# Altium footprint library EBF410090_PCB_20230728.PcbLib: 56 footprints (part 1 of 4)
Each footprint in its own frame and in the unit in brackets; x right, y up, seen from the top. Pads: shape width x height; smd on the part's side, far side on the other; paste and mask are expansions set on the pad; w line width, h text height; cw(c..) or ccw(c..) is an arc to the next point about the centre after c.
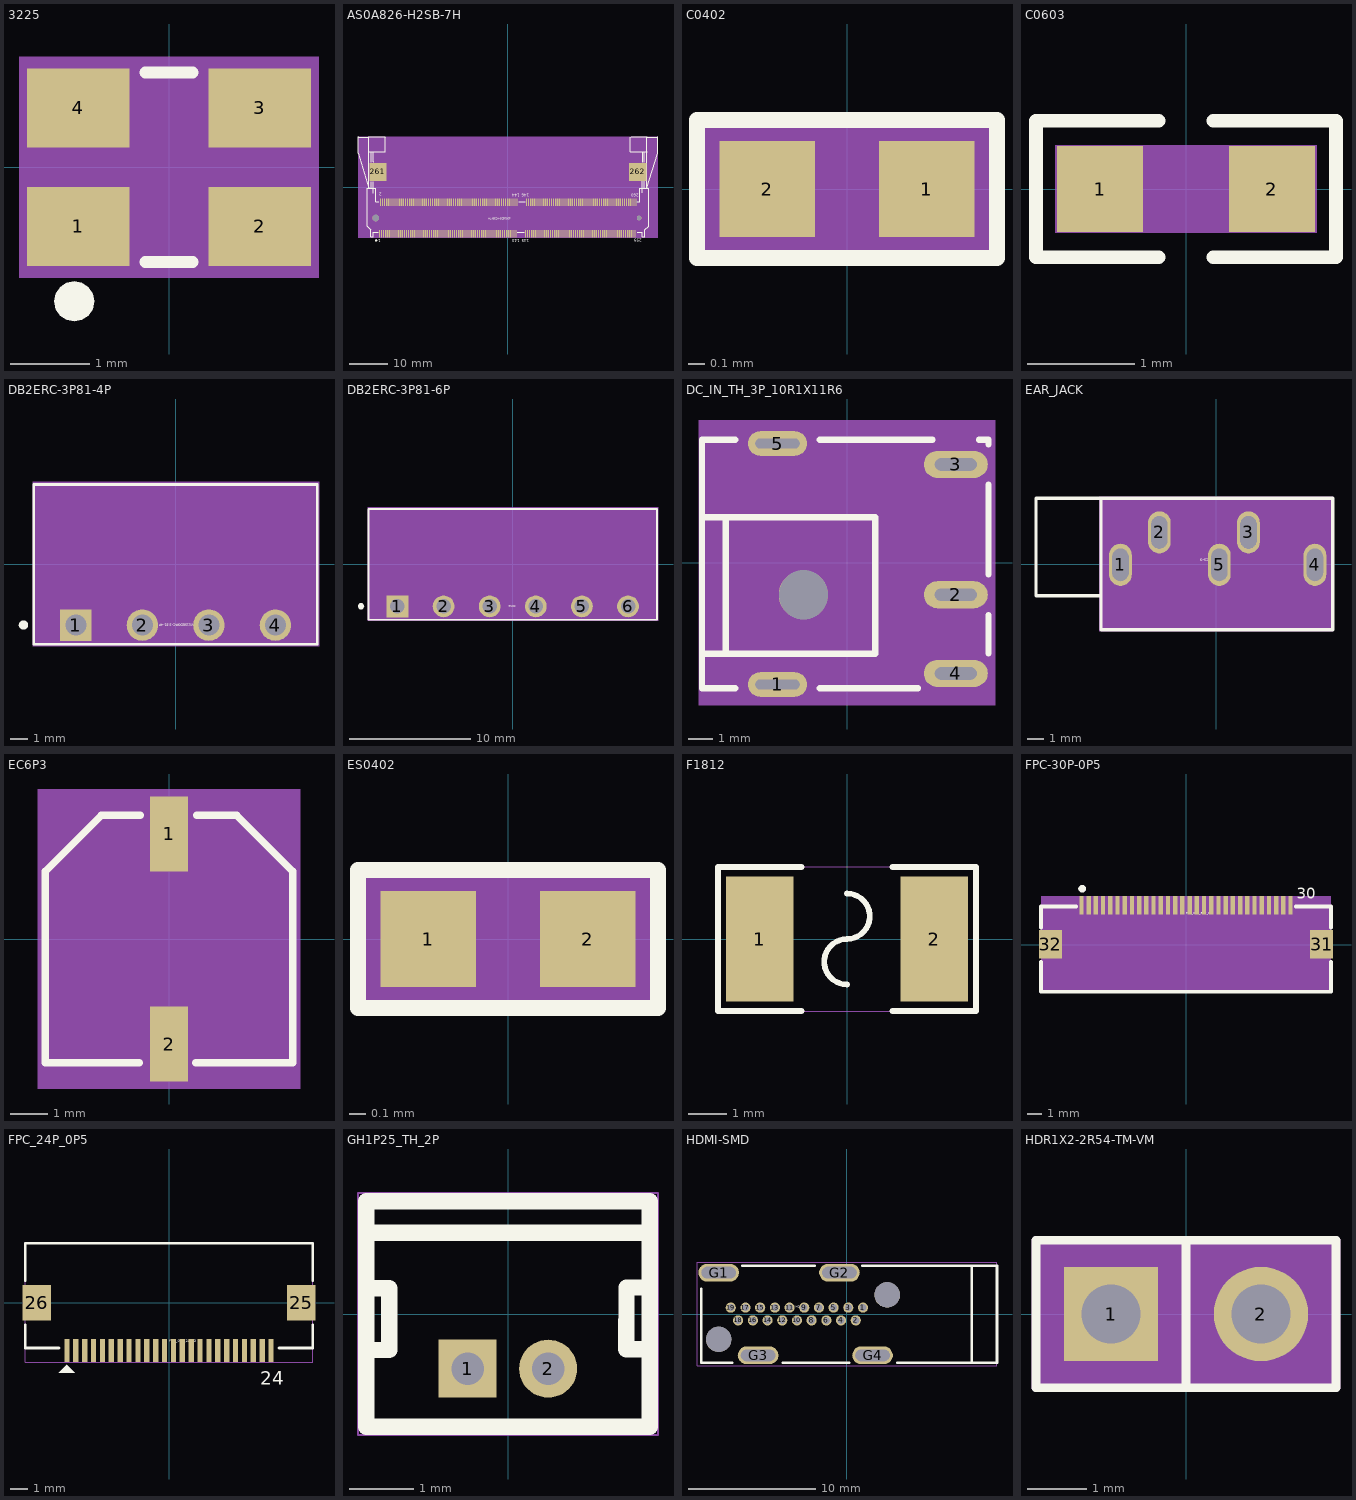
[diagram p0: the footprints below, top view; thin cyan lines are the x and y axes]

## 3225 [mm] "3225"
pads (4):
  rect 1.3x1 smd: 1(-1.15,-0.75) 2(1.15,-0.75) 3(1.15,0.75) 4(-1.15,0.75)
Top Overlay:
  dashed: -0.945,-1.7 -0.964,-1.603 -1.02,-1.52 -1.102,-1.465 -1.2,-1.445 -1.297,-1.465 -1.325,-1.483 -1.38,-1.52 -1.435,-1.603 -1.455,-1.7 -1.435,-1.798 -1.38,-1.88 -1.325,-1.917 -1.297,-1.935 -1.2,-1.955 -1.102,-1.935 -1.02,-1.88 -0.964,-1.798
  lines w0.15: -0.3,-1.2 0.3,-1.2 ; -0.3,1.2 0.3,1.2
Top 3D Body:
  region: -1.9,1.4 -1.9,-1.4 1.9,-1.4 1.9,1.4
Top Assembly:
  lines w0.15: -1.6,-1.25 1.6,-1.25 1.6,1.25 -1.6,1.25 -1.6,-1.25
3D body: height 3.81, standoff 0, extent -1.9,-1.4 1.9,1.4

## AS0A826-H2SB-7H [mm] "AS0A826-H2SB-7H"
pads (264):
  rect 0.3x2 smd: 1(-33.425,-12.1) 2(-33.175,-3.9) 3(-32.925,-12.1) 4(-32.675,-3.9) 5(-32.425,-12.1) 6(-32.175,-3.9) 7(-31.925,-12.1) 8(-31.675,-3.9) 9(-31.425,-12.1) 10(-31.175,-3.9) 11(-30.925,-12.1) 12(-30.675,-3.9) 13(-30.425,-12.1) 14(-30.175,-3.9) 15(-29.925,-12.1) 16(-29.675,-3.9) 17(-29.425,-12.1) 18(-29.175,-3.9) 19(-28.925,-12.1) 20(-28.675,-3.9) 21(-28.425,-12.1) 22(-28.175,-3.9) 23(-27.925,-12.1) 24(-27.675,-3.9) 25(-27.425,-12.1) 26(-27.175,-3.9) 27(-26.925,-12.1) 28(-26.675,-3.9) 29(-26.425,-12.1) 30(-26.175,-3.9) 31(-25.925,-12.1) 32(-25.675,-3.9) 33(-25.425,-12.1) 34(-25.175,-3.9) 35(-24.925,-12.1) 36(-24.675,-3.9) 37(-24.425,-12.1) 38(-24.175,-3.9) 39(-23.925,-12.1) 40(-23.675,-3.9) 41(-23.425,-12.1) 42(-23.175,-3.9) 43(-22.925,-12.1) 44(-22.675,-3.9) 45(-22.425,-12.1) 46(-22.175,-3.9) 47(-21.925,-12.1) 48(-21.675,-3.9) 49(-21.425,-12.1) 50(-21.175,-3.9) 51(-20.925,-12.1) 52(-20.675,-3.9) 53(-20.425,-12.1) 54(-20.175,-3.9) 55(-19.925,-12.1) 56(-19.675,-3.9) 57(-19.425,-12.1) 58(-19.175,-3.9) 59(-18.925,-12.1) 60(-18.675,-3.9) 61(-18.425,-12.1) 62(-18.175,-3.9) 63(-17.925,-12.1) 64(-17.675,-3.9) 65(-17.425,-12.1) 66(-17.175,-3.9) 67(-16.925,-12.1) 68(-16.675,-3.9) 69(-16.425,-12.1) 70(-16.175,-3.9) 71(-15.925,-12.1) 72(-15.675,-3.9) 73(-15.425,-12.1) 74(-15.175,-3.9) 75(-14.925,-12.1) 76(-14.675,-3.9) 77(-14.425,-12.1) 78(-14.175,-3.9) 79(-13.925,-12.1) 80(-13.675,-3.9) 81(-13.425,-12.1) 82(-13.175,-3.9) 83(-12.925,-12.1) 84(-12.675,-3.9) 85(-12.425,-12.1) 86(-12.175,-3.9) 87(-11.925,-12.1) 88(-11.675,-3.9) 89(-11.425,-12.1) 90(-11.175,-3.9) 91(-10.925,-12.1) 92(-10.675,-3.9) 93(-10.425,-12.1) 94(-10.175,-3.9) 95(-9.925,-12.1) 96(-9.675,-3.9) 97(-9.425,-12.1) 98(-9.175,-3.9) 99(-8.925,-12.1) 100(-8.675,-3.9) 101(-8.425,-12.1) 102(-8.175,-3.9) 103(-7.925,-12.1) 104(-7.675,-3.9) 105(-7.425,-12.1) 106(-7.175,-3.9) 107(-6.925,-12.1) 108(-6.675,-3.9) 109(-6.425,-12.1) 110(-6.175,-3.9) 111(-5.925,-12.1) 112(-5.675,-3.9) 113(-5.425,-12.1) 114(-5.175,-3.9) 115(-4.925,-12.1) 116(-4.675,-3.9) 117(-4.425,-12.1) 118(-4.175,-3.9) 119(-3.925,-12.1) 120(-3.675,-3.9) 121(-3.425,-12.1) 122(-3.175,-3.9) 123(-2.925,-12.1) 124(-2.675,-3.9) 125(-2.425,-12.1) 126(-2.175,-3.9) 127(-1.925,-12.1) 128(-1.675,-3.9) 129(-1.425,-12.1) 130(-1.175,-3.9) 131(-0.925,-12.1) 132(-0.675,-3.9) 133(-0.425,-12.1) 134(-0.175,-3.9) 135(0.075,-12.1) 136(0.325,-3.9) 137(0.575,-12.1) 138(0.825,-3.9) 139(1.075,-12.1) 140(1.325,-3.9) 141(1.575,-12.1) 142(1.825,-3.9) 143(2.075,-12.1) 144(2.325,-3.9) 145(4.575,-12.1) 146(4.825,-3.9) 147(5.075,-12.1) 148(5.325,-3.9) 149(5.575,-12.1) 150(5.825,-3.9) 151(6.075,-12.1) 152(6.325,-3.9) 153(6.575,-12.1) 154(6.825,-3.9) 155(7.075,-12.1) 156(7.325,-3.9) 157(7.575,-12.1) 158(7.825,-3.9) 159(8.075,-12.1) 160(8.325,-3.9) 161(8.575,-12.1) 162(8.825,-3.9) 163(9.075,-12.1) 164(9.325,-3.9) 165(9.575,-12.1) 166(9.825,-3.9) 167(10.075,-12.1) 168(10.325,-3.9) 169(10.575,-12.1) 170(10.825,-3.9) 171(11.075,-12.1) 172(11.325,-3.9) 173(11.575,-12.1) 174(11.825,-3.9) 175(12.075,-12.1) 176(12.325,-3.9) 177(12.575,-12.1) 178(12.825,-3.9) 179(13.075,-12.1) 180(13.325,-3.9) 181(13.575,-12.1) 182(13.825,-3.9) 183(14.075,-12.1) 184(14.325,-3.9) 185(14.575,-12.1) 186(14.825,-3.9) 187(15.075,-12.1) 188(15.325,-3.9) 189(15.575,-12.1) 190(15.825,-3.9) 191(16.075,-12.1) 192(16.325,-3.9) 193(16.575,-12.1) 194(16.825,-3.9) 195(17.075,-12.1) 196(17.325,-3.9) 197(17.575,-12.1) 198(17.825,-3.9) 199(18.075,-12.1) 200(18.325,-3.9) 201(18.575,-12.1) 202(18.825,-3.9) 203(19.075,-12.1) 204(19.325,-3.9) 205(19.575,-12.1) 206(19.825,-3.9) 207(20.075,-12.1) 208(20.325,-3.9) 209(20.575,-12.1) 210(20.825,-3.9) 211(21.075,-12.1) 212(21.325,-3.9) 213(21.575,-12.1) 214(21.825,-3.9) 215(22.075,-12.1) 216(22.325,-3.9) 217(22.575,-12.1) 218(22.825,-3.9) 219(23.075,-12.1) 220(23.325,-3.9) 221(23.575,-12.1) 222(23.825,-3.9) 223(24.075,-12.1) 224(24.325,-3.9) 225(24.575,-12.1) 226(24.825,-3.9) 227(25.075,-12.1) 228(25.325,-3.9) 229(25.575,-12.1) 230(25.825,-3.9) 231(26.075,-12.1) 232(26.325,-3.9) 233(26.575,-12.1) 234(26.825,-3.9) 235(27.075,-12.1) 236(27.325,-3.9) 237(27.575,-12.1) 238(27.825,-3.9) 239(28.075,-12.1) 240(28.325,-3.9) 241(28.575,-12.1) 242(28.825,-3.9) 243(29.075,-12.1) 244(29.325,-3.9) 245(29.575,-12.1) 246(29.825,-3.9) 247(30.075,-12.1) 248(30.325,-3.9) 249(30.575,-12.1) 250(30.825,-3.9) 251(31.075,-12.1) 252(31.325,-3.9) 253(31.575,-12.1) 254(31.825,-3.9) 255(32.075,-12.1) 256(32.325,-3.9) 257(32.575,-12.1) 258(32.825,-3.9) 259(33.075,-12.1) 260(33.325,-3.9)
  rect 4.5x4.6 smd: 261(-33.85,4) 262(33.75,4)
  round 1.7 hole 1.7 unplated: ""(-34.45,-8)
  round 1.2 hole 1.2 unplated: ""(34.15,-8)
Top Overlay:
  dashed: -34.575,-13.839 -34.556,-13.936 -34.5,-14.019 -34.418,-14.074 -34.32,-14.094 -34.223,-14.074 -34.195,-14.056 -34.14,-14.019 -34.085,-13.936 -34.065,-13.839 -34.085,-13.741 -34.14,-13.659 -34.195,-13.622 -34.223,-13.604 -34.32,-13.584 -34.418,-13.604 -34.5,-13.659 -34.556,-13.741
  lines w0.15: -36.345,9.25 -31.986,9.25 -31.986,12.962 -32.125,13.1 -36.264,13.1 -36.282,13.083 ; -35.629,6.531 -35.629,9.25 ; -35.575,-0.3 -35.575,1.46 -35.566,1.469 ; -35.112,-1.5 -35.112,1.405 -35.048,1.469 ; -35.112,9.25 -35.112,6.595 -35.048,6.531 ; -33.742,-11.75 -35.05,-11.75 -35.05,-12.9 -35.75,-12.9 -35.75,-11.034 -36.7,-10.084 -36.7,-0.3 -34.45,-0.3 -34.45,-3.717 -33.631,-3.717 ; 2.456,-11.75 4.194,-11.75 ; 2.77,-3.717 4.507,-3.717 ; 33.531,-3.716 34.35,-3.716 34.35,-0.299 36.6,-0.299 36.6,-10.084 35.65,-11.034 35.65,-12.9 34.95,-12.9 34.95,-11.75 33.643,-11.75 ; 34.967,-1.45 34.967,1.519 ; 35.03,6.581 35.03,9.3 ; 35.421,6.581 35.484,6.645 35.484,9.3 ; 35.484,-0.25 35.484,1.519 ; 36.246,9.25 31.887,9.25 31.887,12.962 32.025,13.1 36.165,13.1 36.182,13.083 ; -36.282,13.083 -39.032,13.083 -39.05,13.1 -39.05,8.85 -36.282,-0.3 -36.282,13.083 ; 36.182,13.083 38.933,13.083 38.95,13.1 38.95,8.851 36.182,-0.299 36.182,13.083
  text "144" at 3.043,-1.647 h0.76
  text "143" at 3.043,-13.585 h0.76
  text "146" at 5.583,-1.647 h0.76
  text "145" at 5.583,-13.585 h0.76
  text "259" at 34.793,-13.458 h0.76
  text "260" at 34.031,-1.647 h0.76
  text "1" at -33.177,-13.585 h0.76
  text "2" at -32.923,-1.393 h0.76
  text "AS0A826-H2SB-7H" at 0.765,-7.924 h0.15
Top 3D Body:
  region: -39.05,13.2 -39.05,-13.2 39.05,-13.2 39.05,13.2
Mechanical 16:
  text "65" at -17.345,-12.1 h0.1
  text "67" at -16.845,-12.1 h0.1
  text "96" at -9.595,-3.9 h0.1
  text "32" at -25.595,-3.9 h0.1
  text "21" at -28.345,-12.1 h0.1
  text "19" at -28.845,-12.1 h0.1
  text "29" at -26.345,-12.1 h0.1
  text "27" at -26.845,-12.1 h0.1
  text "153" at 6.645,-12.033 h0.1
  text "51" at -20.845,-12.1 h0.1
  text "75" at -14.845,-12.1 h0.1
  text "73" at -15.345,-12.1 h0.1
  text "71" at -15.845,-12.1 h0.1
  text "69" at -16.345,-12.1 h0.1
  text "100" at -8.455,-3.933 h0.1
  text "98" at -9.095,-3.9 h0.1
  text "105" at -7.255,-12.033 h0.1
  text "107" at -6.755,-12.033 h0.1
  text "117" at -4.255,-12.033 h0.1
  text "119" at -3.755,-12.033 h0.1
  text "121" at -3.255,-12.033 h0.1
  text "123" at -2.755,-12.033 h0.1
  text "113" at -5.255,-12.033 h0.1
  text "115" at -4.755,-12.033 h0.1
  text "109" at -6.255,-12.033 h0.1
  text "111" at -5.755,-12.033 h0.1
  text "50" at -21.095,-3.9 h0.1
  text "54" at -20.095,-3.9 h0.1
  text "52" at -20.595,-3.9 h0.1
  text "48" at -21.595,-3.9 h0.1
  text "184" at 14.545,-3.833 h0.1
  text "22" at -28.095,-3.9 h0.1
  text "209" at 20.745,-12.033 h0.1
  text "58" at -19.095,-3.9 h0.1
  text "176" at 12.445,-3.833 h0.1
  text "31" at -25.845,-12.1 h0.1
  text "33" at -25.345,-12.1 h0.1
  text "76" at -14.595,-3.9 h0.1
  text "90" at -11.095,-3.9 h0.1
  text "64" at -17.595,-3.9 h0.1
  text "34" at -25.095,-3.9 h0.1
  text "30" at -26.095,-3.9 h0.1
  text "78" at -14.095,-3.9 h0.1
  text "13" at -30.345,-12.1 h0.1
  text "5" at -32.385,-12.1 h0.1
  text "136" at 0.545,-3.833 h0.1
  text "14" at -30.095,-3.9 h0.1
  text "148" at 5.445,-3.833 h0.1
  text "12" at -30.595,-3.9 h0.1
  text "23" at -27.845,-12.1 h0.1
  text "16" at -29.595,-3.9 h0.1
  text "25" at -27.345,-12.1 h0.1
  text "26" at -27.095,-3.9 h0.1
  text "11" at -30.845,-12.1 h0.1
  text "161" at 8.745,-12.033 h0.1
  text "163" at 9.245,-12.033 h0.1
  text "262" at 33.87,4 h0.1
  text "261" at -33.73,4 h0.1
  text "144" at 2.445,-3.833 h0.1
  text "134" at 0.045,-3.833 h0.1
  text "124" at -2.455,-3.833 h0.1
  text "102" at -8.055,-3.933 h0.1
  text "94" at -10.095,-3.9 h0.1
  text "74" at -15.095,-3.9 h0.1
  text "80" at -13.595,-3.9 h0.1
  text "56" at -19.595,-3.9 h0.1
  text "60" at -18.595,-3.9 h0.1
  text "38" at -24.095,-3.9 h0.1
  text "2" at -33.135,-3.9 h0.1
  text "254" at 31.945,-3.833 h0.1
  text "252" at 31.445,-3.833 h0.1
  text "250" at 30.945,-3.833 h0.1
  text "234" at 26.945,-3.833 h0.1
  text "228" at 25.445,-3.833 h0.1
  text "220" at 23.445,-3.833 h0.1
  text "206" at 19.945,-3.833 h0.1
  text "198" at 17.945,-3.833 h0.1
  text "180" at 13.445,-3.833 h0.1
  text "164" at 9.545,-3.833 h0.1
  text "146" at 5.045,-3.833 h0.1
  text "253" at 31.745,-12.033 h0.1
  text "251" at 31.245,-12.033 h0.1
  text "249" at 30.745,-12.033 h0.1
  text "237" at 27.745,-12.033 h0.1
  text "229" at 25.645,-12.033 h0.1
  text "207" at 20.245,-12.033 h0.1
  text "193" at 16.745,-12.033 h0.1
  text "179" at 13.245,-12.033 h0.1
  text "169" at 10.745,-12.033 h0.1
  text "157" at 7.745,-12.033 h0.1
  text "145" at 4.745,-12.033 h0.1
  text "143" at 2.245,-12.033 h0.1
  text "125" at -2.255,-12.033 h0.1
  text "77" at -14.345,-12.1 h0.1
  text "63" at -17.845,-12.1 h0.1
  text "53" at -20.345,-12.1 h0.1
  text "15" at -29.845,-12.1 h0.1
  text "1" at -33.385,-12.1 h0.1
  text "103" at -7.755,-12.133 h0.1
  text "7" at -31.885,-12.1 h0.1
  text "9" at -31.385,-12.1 h0.1
  text "44" at -22.595,-3.9 h0.1
  text "192" at 16.445,-3.833 h0.1
  text "171" at 11.245,-12.033 h0.1
  text "205" at 19.745,-12.033 h0.1
  text "191" at 16.245,-12.033 h0.1
  text "159" at 8.245,-12.033 h0.1
  text "203" at 19.245,-12.033 h0.1
  text "175" at 12.245,-12.033 h0.1
  text "41" at -23.345,-12.1 h0.1
  text "99" at -8.845,-12.1 h0.1
  text "101" at -8.255,-12.133 h0.1
  text "172" at 11.445,-3.833 h0.1
  text "233" at 26.845,-12.033 h0.1
  text "89" at -11.345,-12.1 h0.1
  text "46" at -22.095,-3.9 h0.1
  text "83" at -12.845,-12.1 h0.1
  text "177" at 12.745,-12.033 h0.1
  text "85" at -12.345,-12.1 h0.1
  text "189" at 15.745,-12.033 h0.1
  text "95" at -9.845,-12.1 h0.1
  text "186" at 14.945,-3.833 h0.1
  text "240" at 28.545,-3.833 h0.1
  text "239" at 28.245,-12.033 h0.1
  text "97" at -9.345,-12.1 h0.1
  text "242" at 28.945,-3.833 h0.1
  text "241" at 28.745,-12.033 h0.1
  text "244" at 29.445,-3.833 h0.1
  text "243" at 29.245,-12.033 h0.1
  text "174" at 12.045,-3.833 h0.1
  text "178" at 13.045,-3.833 h0.1
  text "183" at 14.245,-12.033 h0.1
  text "246" at 30.045,-3.833 h0.1
  text "245" at 29.745,-12.033 h0.1
  text "149" at 5.645,-12.033 h0.1
  text "168" at 10.545,-3.833 h0.1
  text "17" at -29.345,-12.1 h0.1
  text "170" at 10.945,-3.833 h0.1
  text "195" at 17.245,-12.033 h0.1
  text "59" at -18.845,-12.1 h0.1
  text "197" at 17.745,-12.033 h0.1
  text "199" at 18.245,-12.033 h0.1
  text "201" at 18.745,-12.033 h0.1
  text "8" at -31.635,-3.9 h0.1
  text "181" at 13.745,-12.033 h0.1
  text "211" at 21.245,-12.033 h0.1
  text "24" at -27.595,-3.9 h0.1
  text "196" at 17.545,-3.833 h0.1
  text "190" at 15.945,-3.833 h0.1
  text "79" at -13.845,-12.1 h0.1
  text "61" at -18.345,-12.1 h0.1
  text "81" at -13.345,-12.1 h0.1
  text "87" at -11.845,-12.1 h0.1
  text "57" at -19.345,-12.1 h0.1
  text "55" at -19.845,-12.1 h0.1
  text "36" at -24.595,-3.9 h0.1
  text "91" at -10.845,-12.1 h0.1
  text "93" at -10.345,-12.1 h0.1
  text "232" at 26.545,-3.833 h0.1
  text "140" at 1.545,-3.833 h0.1
  text "187" at 15.245,-12.033 h0.1
  text "156" at 7.545,-3.833 h0.1
  text "147" at 5.345,-12.033 h0.1
  text "151" at 6.245,-12.033 h0.1
  text "173" at 11.745,-12.033 h0.1
  text "155" at 7.245,-12.033 h0.1
  text "43" at -22.845,-12.1 h0.1
  text "188" at 15.445,-3.833 h0.1
  text "158" at 7.945,-3.833 h0.1
  text "45" at -22.345,-12.1 h0.1
  text "248" at 30.445,-3.833 h0.1
  text "247" at 30.245,-12.033 h0.1
  text "236" at 27.445,-3.833 h0.1
  text "238" at 28.045,-3.833 h0.1
  text "216" at 22.445,-3.833 h0.1
  text "214" at 22.045,-3.833 h0.1
  text "165" at 9.745,-12.033 h0.1
  text "152" at 6.545,-3.833 h0.1
  text "212" at 21.445,-3.833 h0.1
  text "160" at 8.545,-3.833 h0.1
  text "154" at 6.945,-3.833 h0.1
  text "210" at 20.945,-3.833 h0.1
  text "162" at 8.945,-3.733 h0.1
  text "218" at 23.045,-3.833 h0.1
  text "208" at 20.545,-3.833 h0.1
  text "166" at 10.045,-3.833 h0.1
  text "4" at -32.635,-3.9 h0.1
  text "39" at -23.845,-12.1 h0.1
  text "142" at 1.945,-3.833 h0.1
  text "235" at 27.245,-12.033 h0.1
  text "18" at -29.095,-3.9 h0.1
  text "230" at 25.945,-3.833 h0.1
  text "185" at 14.745,-12.033 h0.1
  text "20" at -28.595,-3.9 h0.1
  text "194" at 16.945,-3.833 h0.1
  text "200" at 18.445,-3.833 h0.1
  text "204" at 19.545,-3.833 h0.1
  text "104" at -7.555,-3.833 h0.1
  text "106" at -6.955,-3.933 h0.1
  text "116" at -4.555,-3.933 h0.1
  text "118" at -4.055,-3.833 h0.1
  text "120" at -3.455,-3.833 h0.1
  text "122" at -3.055,-3.933 h0.1
  text "114" at -5.055,-3.933 h0.1
  text "112" at -5.455,-3.933 h0.1
  text "108" at -6.455,-3.833 h0.1
  text "167" at 10.245,-12.033 h0.1
  text "110" at -5.955,-3.933 h0.1
  text "35" at -24.845,-12.1 h0.1
  text "37" at -24.345,-12.1 h0.1
  text "3" at -32.885,-12.1 h0.1
  text "150" at 5.945,-3.833 h0.1
  text "227" at 25.245,-12.033 h0.1
  text "225" at 24.745,-12.133 h0.1
  text "224" at 24.545,-3.833 h0.1
  text "223" at 24.245,-12.033 h0.1
  text "221" at 23.745,-12.033 h0.1
  text "127" at -1.755,-12.033 h0.1
  text "129" at -1.255,-12.033 h0.1
  text "42" at -23.095,-3.9 h0.1
  text "131" at -0.755,-12.033 h0.1
  text "40" at -23.595,-3.9 h0.1
  text "133" at -0.255,-12.033 h0.1
  text "226" at 24.945,-3.833 h0.1
  text "135" at 0.245,-12.033 h0.1
  text "202" at 19.045,-3.833 h0.1
  text "137" at 0.845,-12.033 h0.1
  text "139" at 1.145,-12.033 h0.1
  text "222" at 23.945,-3.833 h0.1
  text "141" at 1.745,-12.033 h0.1
  text "126" at -2.055,-3.933 h0.1
  text "62" at -18.095,-3.9 h0.1
  text "66" at -17.095,-3.9 h0.1
  text "68" at -16.595,-3.9 h0.1
  text "70" at -16.095,-3.9 h0.1
  text "72" at -15.595,-3.9 h0.1
  text "49" at -21.345,-12.1 h0.1
  text "128" at -1.555,-3.833 h0.1
  text "47" at -21.845,-12.1 h0.1
  text "182" at 13.945,-3.833 h0.1
  text "138" at 0.945,-3.833 h0.1
  text "28" at -26.595,-3.9 h0.1
  text "84" at -12.595,-3.9 h0.1
  text "82" at -13.095,-3.9 h0.1
  text "92" at -10.595,-3.9 h0.1
  text "88" at -11.595,-3.9 h0.1
  text "86" at -12.095,-3.9 h0.1
  text "231" at 26.245,-12.033 h0.1
  text "130" at -1.055,-3.833 h0.1
  text "6" at -32.135,-3.9 h0.1
  text "10" at -31.095,-3.9 h0.1
  text "132" at -0.555,-3.833 h0.1
  text "260" at 33.545,-3.833 h0.1
  text "258" at 32.945,-3.833 h0.1
  text "256" at 32.545,-3.833 h0.1
  text "259" at 33.245,-12.033 h0.1
  text "257" at 32.745,-12.033 h0.1
  text "255" at 32.245,-12.033 h0.1
  text "219" at 23.245,-12.033 h0.1
  text "217" at 22.745,-12.033 h0.1
  text "215" at 22.245,-12.133 h0.1
  text "213" at 21.745,-12.133 h0.1
Top Assembly:
  dashed: -36.75,-2.8 -36.75,-13.2 36.65,-13.2 36.65,-2.8
3D body: height 3.81, standoff 0, extent -39.05,-13.2 39.05,13.2

## C0402 [mm] "C0402"
pads (2):
  rect 0.599x0.599 smd: 1(0.5,0) 2(-0.5,0)
Top Overlay:
  lines w0.102: -0.94,-0.432 -0.94,0.432 0.94,0.432 0.94,-0.432 -0.94,-0.432
Top 3D Body:
  region: -0.94,-0.432 -0.94,0.432 0.94,0.432 0.94,-0.432
Top Assembly:
  dashed: 0.94,0.432 0.94,-0.432 -0.94,-0.432 -0.94,0.432
3D body: height 3.81, standoff 0, extent -0.94,-0.432 0.94,0.432

## C0603 [mil] "C0603"
pads (2):
  rect 31.5x31.5 smd: 1(-31.5,0) 2(31.5,0)
Top Overlay:
  lines w5: -10,-25 -55,-25 -55,25 -10,25 ; 10,-25 55,-25 55,25 10,25
Top 3D Body:
  region: -48,16 48,16 48,-16 -48,-16
Top Assembly:
  text "C0603" at -117,37 h35
3D body: height 150, standoff 0, extent -48,-16 48,16

## DB2ERC-3P81-4P [mm] "DB2ERC-3P81-4P"
pads (4):
  rect 1.8x1.8 / inner round 1.524 / far side rect 1.8x1.8 hole 1.2: 1(-5.725,-3.5)
  round 1.8 / inner round 1.524 / far side round 1.8 hole 1.2: 2(-1.915,-3.5) 3(1.895,-3.5) 4(5.705,-3.5)
Top Overlay:
  dashed: -8.979,-3.496 -8.96,-3.593 -8.904,-3.676 -8.822,-3.731 -8.724,-3.75 -8.627,-3.731 -8.599,-3.712 -8.544,-3.676 -8.489,-3.593 -8.469,-3.496 -8.489,-3.398 -8.544,-3.315 -8.599,-3.279 -8.627,-3.26 -8.724,-3.241 -8.822,-3.26 -8.904,-3.315 -8.96,-3.398
  lines w0.15: -8.13,-4.6 -8.13,4.55 8.11,4.55 8.11,-4.6 -8.13,-4.6
  text "WJ15EDGRC-3.81-4P" at 1.026,-3.424 h0.15
Top 3D Body:
  region: -8.2,4.7 -8.2,-4.7 8.2,-4.7 8.2,4.7
Mechanical 16:
  text "4" at 5.945,-3.5 h0.6
  text "3" at 2.135,-3.5 h0.6
  text "2" at -1.675,-3.5 h0.6
  text "1" at -5.485,-3.5 h0.6
3D body: height 3.81, standoff 0, extent -8.2,-4.7 8.2,4.7

## DB2ERC-3P81-6P [mm] "DB2ERC-3P81-6P"
pads (6):
  rect 1.8x1.8 / inner round 1.524 / far side rect 1.8x1.8 hole 1.2: 1(-9.525,-3.5)
  round 1.8 hole 1.2: 2(-5.715,-3.5) 5(5.715,-3.5)
  round 1.8 / inner round 1.524 / far side round 1.8 hole 1.2: 3(-1.905,-3.5) 4(1.905,-3.5) 6(9.525,-3.5)
Top Overlay:
  dashed: -12.786,-3.496 -12.767,-3.593 -12.711,-3.676 -12.628,-3.731 -12.531,-3.751 -12.433,-3.731 -12.405,-3.713 -12.35,-3.676 -12.295,-3.593 -12.276,-3.496 -12.295,-3.398 -12.35,-3.315 -12.405,-3.278 -12.433,-3.26 -12.531,-3.24 -12.628,-3.26 -12.711,-3.315 -12.767,-3.398
  lines w0.15: -11.93,-4.6 -11.93,4.55 11.93,4.55 11.93,-4.6 -11.93,-4.6
  text "CON6" at 0.244,-3.424 h0.15
Top 3D Body:
  region: -12,4.7 -12,-4.7 12,-4.7 12,4.7
Mechanical 16:
  text "1" at -9.285,-3.5 h0.6
  text "3" at -1.665,-3.5 h0.6
  text "6" at 9.765,-3.5 h0.6
  text "4" at 2.145,-3.5 h0.6
  text "2" at -5.475,-3.5 h0.6
  text "5" at 5.955,-3.5 h0.6
3D body: height 3.81, standoff 0, extent -12,-4.7 12,4.7

## DC_IN_TH_3P_10R1X11R6 [mil] "DC_IN_TH_3P_10R1X11R6"
pads (6):
  oval 94.5x39.4 hole 70.9 slot 15.7 at 90 deg: 1(-111.25,-194.9) 5(-111.25,190.9)
  oval 102.4x43.3 hole 66.9 slot 19.7 at 90 deg: 2(174.25,-51.2) 3(174.25,157.4)
  oval 102.4x43.3 / inner round 60 / far side oval 102.4x43.3 hole 66.9 slot 19.7 at 90 deg: 4(174.25,-177.2)
  round 78.7 hole 78.7 unplated: ""(-69.85,-51.2)
Top Overlay:
  lines w10: -232.25,-145.7 45.25,-145.7 45.25,72.8 -222.45,72.8 -232.25,72.8 ; -193.95,-145.7 -193.95,72.8 ; -178.95,-200.8 -232.25,-200.8 -232.25,196.8 -178.95,196.8 ; -43.45,-200.8 113.65,-200.8 ; -43.45,196.8 136.95,196.8 ; 211.45,196.8 226.35,196.8 226.35,189.7 ; 226.35,-145 226.35,-83.5 ; 226.35,-19 226.35,125.2
Top 3D Body:
  region: -237.25,-228.4 237.25,-228.4 237.25,228.4 -237.25,228.4
Mechanical 16:
  text "4" at 174.25,-187.2 h25
  text "5" at -111.25,180.9 h25
  text "1" at -111.25,-204.9 h25
  text "2" at 174.25,-61.2 h25
  text "3" at 174.25,147.4 h25
Mechanical 24:
  dashed: -232.25,-141.8 41.35,-141.8 41.35,68.9 -232.25,68.9 -232.25,78.7 51.15,78.7 51.15,-151.6 -232.25,-151.6
3D body: height 150, standoff 0, extent -237.25,-228.4 237.25,228.4

## EAR_JACK [mm] "EAR_JACK"
pads (5):
  oval 1.4x2.6 / inner round 1.524 / far side oval 1.4x2.6 hole 1 slot 2 at 90 deg: 1(-5.904,-0.05) 2(-3.504,1.95) 3(1.996,1.95) 4(6.096,-0.05) 5(0.196,-0.05)
Top Overlay:
  lines w0.2: -7.18,-1.956 -11.117,-1.956 -11.117,4.064 -7.18,4.064 7.196,4.064 7.196,-4.064 -7.104,-4.064 -7.104,4.064
  text "PJ-325C5-G" at 0.196,0.317 h0.15
Top 3D Body:
  region: -7.2,-4.15 7.2,-4.15 7.2,4.15 -7.2,4.15
Mechanical 16:
  text "1" at -5.904,-0.304 h0.64
  text "2" at -3.504,1.696 h0.64
  text "3" at 1.996,1.696 h0.64
  text "5" at 0.196,-0.304 h0.64
  text "4" at 6.096,-0.304 h0.64
Top Assembly:
  dashed: -7.2,4.15 -7.2,-4.15 7.2,-4.15 7.2,4.15
3D body: height 3.81, standoff 0, extent -7.2,-4.15 7.2,4.15

## EC6P3 [mm] "EC6P3"
pads (2):
  rect 1.001x1.999 smd: 1(0,2.8) 2(0,-2.8)
Top Overlay:
  lines w0.2: -0.787,-3.3 -3.3,-3.3 -3.3,1.8 -1.8,3.3 -0.762,3.3 ; 0.711,-3.3 3.3,-3.3 3.3,1.8 1.8,3.3 0.737,3.3
Top 3D Body:
  region: -3.5,4 -3.5,-4 3.5,-4 3.5,4
Mechanical 16:
  text "1" at 0.356,2.8 h0.89
3D body: height 3.81, standoff 0, extent -3.5,-4 3.5,4

## ES0402 [mm] "ES0402"
pads (2):
  rect 0.599x0.599 smd: 1(-0.5,0) 2(0.5,0)
Top Overlay:
  lines w0.102: -0.94,-0.432 -0.94,0.432 0.94,0.432 0.94,-0.432 -0.94,-0.432
Top 3D Body:
  region: 0.94,0.432 0.94,-0.432 -0.94,-0.432 -0.94,0.432
Top Assembly:
  dashed: -0.94,-0.432 -0.94,0.432 0.94,0.432 0.94,-0.432
3D body: height 3.81, standoff 0, extent -0.94,-0.432 0.94,0.432

## F1812 [mm] "F1812"
pads (2):
  rect 1.78x3.3 smd: 1(-2.305,0) 2(2.305,0)
Top Overlay:
  lines w0.15: -1.2,-1.9 -3.4,-1.9 -3.4,1.9 -1.2,1.9 ; 0,-1.2 cw(c0,-0.6) 0,0 ccw(c0,0.6) 0,1.2 ; 1.2,-1.9 3.4,-1.9 3.4,1.9 1.2,1.9
Top 3D Body:
  lines w0.025: -3.4,-1.9 -3.4,1.9 3.4,1.9 3.4,-1.9 -3.4,-1.9
Mechanical 16:
  text "1" at -2.427,0 h0.3
  text "2" at 2.183,0 h0.3

## FPC-30P-0P5 [mm] "FPC-30P-0P5"
pads (32):
  rect 0.3x1.3 smd: 1(-7.25,2.733) 2(-6.75,2.733) 3(-6.25,2.733) 4(-5.75,2.733) 5(-5.25,2.733) 6(-4.75,2.733) 7(-4.25,2.733) 8(-3.75,2.733) 9(-3.25,2.733) 10(-2.75,2.733) 11(-2.25,2.733) 12(-1.75,2.733) 13(-1.25,2.733) 14(-0.75,2.733) 15(-0.25,2.733) 16(0.25,2.733) 17(0.75,2.733) 18(1.25,2.733) 19(1.75,2.733) 20(2.25,2.733) 21(2.75,2.733) 22(3.25,2.733) 23(3.75,2.733) 24(4.25,2.733) 25(4.75,2.733) 26(5.25,2.733) 27(5.75,2.733) 28(6.25,2.733) 29(6.75,2.733) 30(7.25,2.733)
  rect 1.6x2 smd: 31(9.4,0.033) 32(-9.4,0.033)
Top Overlay:
  dashed: -7.2,3.628 -7.102,3.647 -7.02,3.702 -6.964,3.785 -6.945,3.883 -6.964,3.98 -6.983,4.008 -7.02,4.063 -7.102,4.118 -7.2,4.138 -7.298,4.118 -7.38,4.063 -7.417,4.008 -7.436,3.98 -7.455,3.883 -7.436,3.785 -7.38,3.702 -7.298,3.647
  lines w0.254: -10.05,-1.199 -10.05,-3.257 ; -10.05,1.164 -10.05,2.653 -7.631,2.653 ; 7.631,2.653 10.05,2.653 10.05,1.164 ; 10.05,-1.199 10.05,-3.267 -10.04,-3.267 -10.05,-3.258 ; -10.05,-3.258 -10.05,-3.257
  text "30" at 7.671,3.176 h0.76
  text "FPC_0R5_30P_D" at 0,2.099 h0.15
Top 3D Body:
  region: 10.052,-3.35 10.052,3.35 -10.052,3.35 -10.052,-3.35
Mechanical 16:
  text "4" at -5.75,2.813 h0.1
  text "5" at -5.25,2.813 h0.1
  text "1" at -7.25,2.813 h0.1
  text "2" at -6.75,2.813 h0.1
  text "3" at -6.25,2.813 h0.1
  text "10" at -2.75,2.893 h0.1
  text "9" at -3.25,2.813 h0.1
  text "15" at -0.25,2.893 h0.1
  text "17" at 0.75,2.893 h0.1
  text "18" at 1.25,2.893 h0.1
  text "20" at 2.25,2.893 h0.1
  text "21" at 2.75,2.893 h0.1
  text "23" at 3.75,2.893 h0.1
  text "24" at 4.25,2.893 h0.1
  text "26" at 5.25,2.893 h0.1
  text "27" at 5.75,2.893 h0.1
  text "29" at 6.75,2.893 h0.1
  text "30" at 7.25,2.893 h0.1
  text "32" at -10.16,0.113 h0.1
  text "31" at 8.89,0.113 h0.1
  text "6" at -4.75,2.813 h0.1
  text "7" at -4.25,2.813 h0.1
  text "8" at -3.75,2.813 h0.1
  text "16" at 0.25,2.893 h0.1
  text "19" at 1.75,2.893 h0.1
  text "22" at 3.25,2.893 h0.1
  text "25" at 4.75,2.893 h0.1
  text "28" at 6.25,2.893 h0.1
  text "13" at -1.25,2.893 h0.1
  text "11" at -2.25,2.893 h0.1
  text "12" at -1.75,2.893 h0.1
  text "14" at -0.75,2.893 h0.1
3D body: height 3.81, standoff 0, extent -10.052,-3.35 10.052,3.35

## FPC_24P_0P5 [mm] "FPC_24P_0P5"
pads (26):
  rect 0.3x1.3 smd: 1(-5.75,-2.701) 2(-5.25,-2.701) 3(-4.75,-2.701) 4(-4.25,-2.701) 5(-3.75,-2.701) 6(-3.25,-2.701) 7(-2.75,-2.701) 8(-2.25,-2.701) 9(-1.75,-2.701) 10(-1.25,-2.701) 11(-0.75,-2.701) 12(-0.25,-2.701) 13(0.25,-2.701) 14(0.75,-2.701) 15(1.25,-2.701) 16(1.75,-2.701) 17(2.25,-2.701) 18(2.75,-2.701) 19(3.25,-2.701) 20(3.75,-2.701) 21(4.25,-2.701) 22(4.75,-2.701) 23(5.25,-2.701) 24(5.75,-2.701)
  rect 1.6x2 smd: 25(7.45,0.001) 26(-7.45,0.001)
Top Overlay:
  dashed: -6.199,-3.95 -5.301,-3.95 -5.75,-3.501
  lines w0.15: -8.1,-1.25 -8.1,-2.55 -6.2,-2.55 ; -8.1,1.25 -8.1,3.35 8.1,3.35 8.1,1.25 ; 6.2,-2.55 8.1,-2.55 8.1,-1.25
  text "24" at 5.131,-4.618 h0.76
  text "FPC_0P5_24P_D" at 0,-2.219 h0.15
Top 3D Body:
  lines w0.025: -8.1,-3.35 8.1,-3.35 8.1,3.35 -8.1,3.35 -8.1,-3.35
Mechanical 16:
  text "13" at 0.25,-3.209 h0.64
  text "14" at 0.75,-3.209 h0.64
  text "3" at -4.75,-2.955 h0.64
  text "2" at -5.25,-2.955 h0.64
  text "1" at -5.75,-2.955 h0.64
  text "6" at -3.25,-2.955 h0.64
  text "7" at -2.75,-2.955 h0.64
  text "8" at -2.25,-2.955 h0.64
  text "9" at -1.75,-2.955 h0.64
  text "10" at -1.25,-3.209 h0.64
  text "11" at -0.75,-3.209 h0.64
  text "12" at -0.25,-3.209 h0.64
  text "26" at -7.45,-0.507 h0.64
  text "25" at 7.45,-0.507 h0.64
  text "24" at 5.75,-3.209 h0.64
  text "23" at 5.25,-3.209 h0.64
  text "21" at 4.25,-3.209 h0.64
  text "18" at 2.75,-3.209 h0.64
  text "4" at -4.25,-2.955 h0.64
  text "15" at 1.25,-3.209 h0.64
  text "22" at 4.75,-3.209 h0.64
  text "5" at -3.75,-2.955 h0.64
  text "16" at 1.75,-3.209 h0.64
  text "17" at 2.25,-3.209 h0.64
  text "19" at 3.25,-3.209 h0.64
  text "20" at 3.75,-3.209 h0.64

## GH1P25_TH_2P [mm] "GH1P25_TH_2P"
pads (2):
  rect 0.9x0.9 / inner round 1.524 / far side rect 0.9x0.9 hole 0.5: 1(-0.626,-0.849)
  round 0.9 hole 0.5: 2(0.624,-0.849)
Top Overlay:
  lines w0.254: -2.202,0.401 -1.841,0.401 -1.841,-0.559 -2.161,-0.559 ; -2.201,1.262 2.199,1.262 ; 2.159,-0.549 1.839,-0.548 1.839,0.411 2.2,0.411 ; 2.199,-1.749 -2.201,-1.749 -2.201,1.751 2.199,1.751 ; 2.202,-1.751 2.202,1.749
Bottom Overlay:
  lines w0.2: -0.001,-1.549 -0.001,-0.149
  lines w0.3: -1.401,-1.549 -1.101,-1.549 1.399,-1.549 1.399,-0.149 -1.401,-0.149 -1.401,-1.549
Top 3D Body:
  lines w0.025: -2.329,-1.878 -2.329,1.878 2.329,1.878 2.329,-1.878 -2.329,-1.878
Mechanical 16:
  text "1" at -0.88,-0.849 h0.64
  text "2" at 0.37,-0.849 h0.64

## HDMI-SMD [mil] "HDMI-SMD"
pads (25):
  round 31.5 / inner round 60 / far side round 31.5 hole 21.65: 1(50.23,19.69) 3(4.76,19.69) 4(-17.68,-19.68) 6(-63.19,-19.68) 7(-86.18,19.69) 9(-131.65,19.69) 10(-154.21,-19.68) 12(-199.72,-19.68) 13(-222.6,19.69) 14(-245.23,-19.68) 15(-268.08,19.69) 16(-290.75,-19.68) 18(-336.26,-19.68) 19(-359.01,19.69)
  round 31.5 hole 21.65: 2(27.84,-19.68) 5(-40.71,19.69) 8(-108.7,-19.68) 11(-177.13,19.69) 17(-313.54,19.69)
  oval 125.98x55.12 / inner round 60 / far side oval 125.98x55.12 hole 106.3 slot 35.43 at 90 deg: G1(-396.62,127.96) G2(-22.6,127.96) G3(-274.57,-127.95) G4(79.77,-127.95)
  round 78.7 hole 78.7 unplated: ""(-396.62,-78.74) ""(125.03,59.06)
Top Overlay:
  lines w7.87: -449.98,78.74 -449.98,-150.91 -355.28,-150.91 ; -323.36,149.06 -99.81,149.06 ; -197.8,-150.94 6.92,-150.94 ; 48.53,149.06 465.03,149.06 ; 156.53,-150.94 465.03,-150.94 ; 465.03,-150.94 465.03,149.06 ; 465.03,-150.94 386.29,-150.94 386.29,149.06 465.03,149.06
  text "HDMI-001C" at -158.43,18.6 h6
Bottom Overlay:
  drawing of 19 lines, arcs and shapes, not listed
Top Assembly:
  lines w1: -463.61,-159.51 -463.61,159.52 463.62,159.52 463.62,-159.51 -463.61,-159.51

## HDR1X2-2R54-TM-VM [mm] "HDR1X2-2R54-TM-VM"
pads (2):
  rect 1.6x1.6 / inner round 1.524 / far side rect 1.6x1.6 hole 1: 1(-1.27,0)
  round 1.6 / inner round 1.524 / far side round 1.6 hole 1: 2(1.27,0)
Top Overlay:
  lines w0.15: 0,-1.25 0,1.25 ; -2.54,-1.25 -2.54,1.25 2.54,1.25 2.54,-1.25 -2.54,-1.25
Bottom Overlay:
  lines w0.5: 0,-0.55 0,0.55
Top 3D Body:
  region: -2.54,1.25 -2.54,-1.25 2.54,-1.25 2.54,1.25
Mechanical 16:
  text "2" at 1.016,0 h0.64
  text "1" at -1.524,0 h0.64
Top Assembly:
  lines w0.15: -2.54,-1.25 -2.54,1.25 2.54,1.25 2.54,-1.25 -2.54,-1.25
3D body: height 3.81, standoff 0, extent -2.54,-1.25 2.54,1.25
